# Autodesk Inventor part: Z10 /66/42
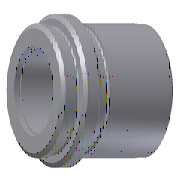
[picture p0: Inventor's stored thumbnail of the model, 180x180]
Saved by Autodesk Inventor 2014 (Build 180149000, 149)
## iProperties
IsCustomPart: 0
Created: 2009-11
Part Number: Z10 /66/42
Material: DIN 1.7131
Description: guide bush
Document SubType Name: Modeling
Designer: gaom
Standard Revision: 1
Manufacturer: HASCO
Language: en-US
Size Designation: 66/42
Categories: <MemberInstance><Categories><Category DisplayName="Mold" InternalName="349578f2-f4d4-4954-8c09-8e99297a61c0" Mnemonic="MOLD"><Category DisplayName="Guide Compon
Density: 7.85 g/cm^3
Appearance: Default
Author: gaom
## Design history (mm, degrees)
sketch "Sketch1"
  geometry: L1 (0, -16.8)-(0, 9.8) reference; L2 (0, 22)-(27, 22); L3 (27, 22)-(27, 11); L4 (27, 11)-(26.5, 11); L5 (26.5, 11)-(26.5, 10); L6 (26.5, 10)-(30, 10); L7 (30, 10)-(30, 0); L8 (30, 0)-(26.5, 0); L9 (26.5, 0)-(26.5, -1); L10 (26.5, -1)-(27, -1); L11 (27, -1)-(27, -55); L12 (27, -55)-(26.95, -55); L13 (26.95, -55)-(26.95, -56); L14 (26.95, -56)-(0, -56); L15 (0, 22)-(0, -56); 1 further point
  constraints: 28 end point, 7 parallel, 5 perpendicular, 2 collinear, 2 equal length, 2 point on line, 1 horizontal alignment
  dimensions: "d0" = 54 diameter of L11 L1 (= D); "d2" = 1 distance between parallel lines of L14 L12; "d27" = 53.9 diameter of L13 L1 (= D_Guide); "d4" = 60 diameter of L7 L1 (= D2); "d5" = 54 diameter of L3 L1 (= D1); "d6" = 10 distance between parallel lines of L8 L6 (= H_); "d7" = 66 distance between parallel lines of L14 L6 (= L); "d8" = 12 distance between parallel lines of L6 L2 (= L1); "d9" = 1 distance between parallel lines of L10 L8; "d10" = 0.5 distance between parallel lines of L11 L9
revolve "Revolution1" sketch "Sketch1" stored, may be unused: angle "d11" = 90 deg
sketch "Sketch2"
  geometry: L1 (-26.95, -56)-(26.95, -56) reference; L2 (21, -56)-(21, 22); L3 (21, 22)-(21, 22); L4 (21, 22)-(21, 100); L5 (0, -56)-(0, 100); L6 (0, 100)-(21, 100); L7 (21, -56)-(0, -56)
  constraints: 12 end point, 3 perpendicular, 2 collinear, 1 midpoint, 1 parallel, 1 point on line
  dimensions: "d12" = 42 diameter of L2 L5 (= d_); "d13" = 78 distance of L2.start L2.end (= l_); "d14" = 78 distance of L3.end L4.end (= L + L1); "d15" = 42 diameter of L4 L5 (= d3)
revolve "Revolution2" sketch "Sketch2" stored, may be unused: angle "d16" = 90 deg
chamfer "Chamfer1" distance "d17" = 0.5; stored, may be unused: second distance "d18" = 2, angle "d19" = 45 deg
fillet "Fillet1" dims "d20" = 0.3
fillet "Fillet2" dims "d21" = 0.8
body "Solid1"
other parameters: "d_" = 42 [user parameter; used in 1 equation term], "L" = 66 [user parameter; used in 2 equation terms], "D" = 54 [user parameter; used in 1 equation term], "D1" = 54 [user parameter; used in 1 equation term], "D2" = 60 [user parameter; used in 1 equation term], "H_" = 10 [user parameter; used in 1 equation term], "L1" = 12 [user parameter; used in 2 equation terms], "l_" = 78 [user parameter; used in 1 equation term], "d3" = 42 [user parameter; used in 1 equation term], "D_Guide" = 53.9 [user parameter; used in 1 equation term], "d22" = 0, "d23" = 0, "d24" = 0, "d25" = 0, "d26" = 0
